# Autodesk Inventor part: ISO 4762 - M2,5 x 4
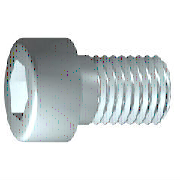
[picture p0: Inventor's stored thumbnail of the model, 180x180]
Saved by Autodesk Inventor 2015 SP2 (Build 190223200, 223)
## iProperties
Created: 2012-02
Part Number: ISO 4762 - M2,5 x 4
Material: Edelstahl, 440C
Description: Innensechskantschraube
Document SubType Name: Modeling
Standard: ISO 4762
Designer: rmaryll
Standard Revision: Fourth edition 2004-03-01
Standards Organization: ISO
Language: de-DE
Size Designation: M2,5 x 4
Categories: <MemberInstance><Categories><Category DisplayName="Verbindungselemente" InternalName="e4da775c-781d-43d5-af7c-5136215cf5a6" Mnemonic="FSTN"><Category DisplayNam
Density: 7.75 g/cm^3
Appearance: Halbpoliert
IsCustomPart: 0
Author: rmaryll
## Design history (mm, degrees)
sketch "Skizze1"
  geometry: L1 (-0.733, 0)-(4, 0); L2 (4, 0)-(4, 1.25); L3 (4, 1.25)-(1.125, 1.25); L4 (1.125, 1.25)-(0.849, 1.25); L5 (0.849, 1.25)-(0, 1.25); L6 (0, 1.25)-(0, 2.25); L7 (0, 2.25)-(-2.5, 2.25); L8 (-2.5, 2.25)-(-2.5, 1.155); L9 (-2.5, 1.155)-(-1.4, 1.155); L10 (-1.4, 1.155)-(-0.733, 0); L11 (-3.8, 0)-(5.3, 0) reference; L12 (0, -0.45)-(0, 2.7) reference; L13 (1.125, 1.25)-(0, 1.25)
  constraints: 22 end point, 6 parallel, 2 collinear, 2 perpendicular, 1 horizontal, 1 point on line
  dimensions: "d1" = 2.875 distance from line of L3.end L2 (= GEL); "d2" = 0.27615 distance of L4.end L3.end (computed from GAL); "d3" = 2.5 distance between parallel lines of L8 L6 (= KOH); "d4" = 1.1 distance of L8.end L9.end (= INTI); "d5" = 60 deg angle of L10 L1; "d6" = 2.5 diameter of L3 L1 (= GD); "d7" = 2.5 diameter of L5 L1 (= BDM); "d8" = 2.3094 diameter of L9 L1 (= 1.1547 x SW); "d9" = 4.5 diameter of L7 L1 (= KOD); "d26" = 4 distance between parallel lines of L12 L2 (= NLG)
revolve "Körper" sketch "Skizze1" stored, may be unused: angle "d10" = 90 deg
sketch "Skizze2"
  geometry: L1 (0, -3.15)-(0, 3.15) reference; L2 (-3.15, 0)-(3.15, 0) reference; L3 (1.155, 0)-(0.577, -1); L4 (0.577, -1)-(-0.577, -1); L5 (-0.577, -1)-(-1.155, 0); L6 (-1.155, 0)-(-0.577, 1); L7 (-0.577, 1)-(0.577, 1); L8 (0.577, 1)-(1.155, 0); 2 further points
  constraints: 12 end point, 1 coincident, 1 horizontal alignment, 1 point on line, 12 other
extrude "Loch" join sketch "Skizze2" stored distance "d11" = 10; taper "d12" = 0 deg
workplane "Work Plane1"
fillet "Fillet2" dims "d30" = 0.1 (= R)
body "Solid1"
fillet "Rundung1" dims "d17" = 0.25 (= RR)
feature "Gewinde" dims "d13" = 2.875 (= GEL), "d14" = 0
chamfer "Fase1" distance "d15" = 0.27605 (= -0.5 x SPD + 0.5 x GD); stored, may be unused: second distance "d16" = 0.27605 (= GUL), angle "d27" = 45 deg
other parameters: "GD" = 2.5 [user parameter; used in 2 equation terms], "NLG" = 4 [user parameter; used in 1 equation term], "GEL" = 2.875 [user parameter; used in 2 equation terms], "KOD" = 4.5 [user parameter; used in 1 equation term], "KOH" = 2.5 [user parameter; used in 1 equation term], "INTI" = 1.1 [user parameter; used in 1 equation term], "GAL" = 0.27605 (= 0.61345 x PTC) [user parameter; used in 1 equation term], "GUL" = 0.27605 (= 0.61345 x PTC) [user parameter; used in 1 equation term], "BDM" = 2.5 (= NND) [user parameter; used in 1 equation term], "SW" = 2 [user parameter; used in 2 equation terms], "RR" = 0.25 [user parameter; used in 1 equation term], "SPD" = 1.94789 (= NND - 1.2269 x PTC) [user parameter; used in 1 equation term], "d19" = 0, "d28" = 0, "d29" = 0, "R" = 0.1 [user parameter; used in 1 equation term], "TOA" = 30 deg [user parameter], "GD1" = 1.94789 (= THREADDIA - 1.2269 x PTC) [user parameter], "THREADDIA" = 2.5 [user parameter; used in 1 equation term], "FAWI" = 45 deg [user parameter], "TPU" = 22.22222 (computed from PTC) [user parameter], "PTC" = 0.45 [user parameter; used in 5 equation terms], "NND" = 2.5 [user parameter; used in 2 equation terms], "E0" = 2.31 (= 1.155 x SW) [user parameter]
